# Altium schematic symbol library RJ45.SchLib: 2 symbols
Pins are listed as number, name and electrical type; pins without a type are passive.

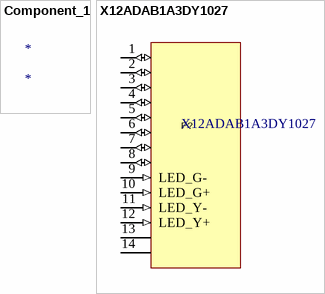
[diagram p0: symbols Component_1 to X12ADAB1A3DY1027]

## Component_1
designator *

## X12ADAB1A3DY1027
designator P?
Manufacturer: XKB Connection(中国星坤); Add into BOM: yes; Connector Type: RJ45插座; Number of Ports: 1; Shielding: 有屏蔽; LED: 带LED; Soldering Temperature(Max): 260℃
footprint RJ45-TH_XKB_X12ADAB1A3DY1027
pins: 1 (io), 2 (io), 3 (io), 4 (io), 5 (io), 6 (io), 7 (io), 8 (io), 9 LED_G- (in), 10 LED_G+ (in), 11 LED_Y- (in), 12 LED_Y+ (in), 13, 14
